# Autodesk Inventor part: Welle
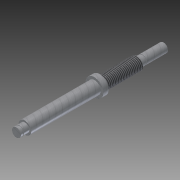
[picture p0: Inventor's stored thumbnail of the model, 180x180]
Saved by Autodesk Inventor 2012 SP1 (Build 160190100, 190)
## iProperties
Created: 2012-10
Part Number: Welle
Material: Default
Document SubType Name: Modeling
Designer: Dominic Mähling
Density: 1 g/cm^3
Author: Dominic Mähling
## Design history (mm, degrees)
derived "Funkenstrecke master.ipt"
feature "Welle::Funkenstrecke master.ipt" dims "d0" = 10
tag "Bezeichnung1"
node "Volumenkörper1"
